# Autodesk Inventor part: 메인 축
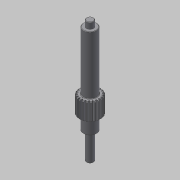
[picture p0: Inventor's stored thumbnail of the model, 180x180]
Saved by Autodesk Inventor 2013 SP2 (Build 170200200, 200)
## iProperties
Created: 2016-02
Part Number: 메인 축
Material: 일반
Document SubType Name: Modeling
Categories: <?xml version="1.0" encoding="UTF-16"?> <MemberInstance><Categories><FamilyTemplate><FamilyTemplateParameter ValueType="xs:double" Id="1" ObjectReferenceKey="da
Density: 1 g/cm^3
Mass: 187.503 g
Surface Area: 82.0529 cm^2
Volume: 23.8554 cm^3
Author: mdu
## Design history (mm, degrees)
sketch "Sketch1"
  geometry: C1 r 12 at (0, 0)
  constraints: 1 centre point
  dimensions: "d0" = 24 diameter of C1 (= da_da)
extrude "Extrusion1" new body sketch "Sketch1" distance "d1" = 20 (= da_b); taper "d2" = 0 deg
workplane "Work Plane2"
feature "피치 지름" dims "d4" = 10, "d5" = 0
workplane "Work Plane8"
workplane "Work Plane9"
chamfer "모따기1" distance "d49" = 1; stored, may be unused: second distance "d50" = 2, angle "d51" = 45 deg
sketch "스케치3"
  geometry: C1 r 7.5 at (0, 0); 1 further point
  constraints: 1 centre point, 1 coincident
  dimensions: "d52" = 15 diameter of C1
extrude "돌출2" join sketch "스케치3" distance "d53" = 66; taper "d54" = 0 deg
sketch "스케치4"
  geometry: C1 r 4 at (0, 0); 1 further point
  constraints: 1 centre point, 1 coincident
  dimensions: "d55" = 8 diameter of C1
extrude "돌출3" join sketch "스케치4" distance "d56" = 7; taper "d57" = 0 deg
sketch "스케치5"
  geometry: C1 r 7.5 at (0, 0) reference; C2 r 7.5 at (0, 0) reference; 1 further point
extrude "돌출4" join sketch "스케치5" distance "d62" = 16; taper "d63" = 0 deg
sketch "스케치6"
  geometry: C1 r 4 at (0, 0); 1 further point
  constraints: 1 centre point, 1 coincident
  dimensions: "d64" = 8 diameter of C1
extrude "돌출5" join sketch "스케치6" distance "d65" = 30; taper "d66" = 0 deg
chamfer "모따기2" distance "d58" = 0.5; stored, may be unused: second distance "d59" = 2, angle "d60" = 45 deg
fillet "모깎기1" dims "d61" = 0.5
feature "스퍼 기어" dims "da_b" = 20, "da_d" = 22, "da_aw" = 31, "da_da" = 24, "da_df" = 19.5, "da_dw" = 22, angle "da_beta" = 0 deg, "da_lefttooth" = 0, "da_righttooth" = 0
sketch "스케치7" dims "d68" = 18
  geometry: C1 r 0.25 at (0, -9); 2 further points
  constraints: 2 vertical alignment, 1 centre point, 1 coincident, 2 other
  dimensions: "d67" = 0.5 diameter of C1
extrude "돌출6" join sketch "스케치7" distance "d69" = 0.3; taper "d70" = 0 deg
body "Solid1"
sketch "Sketch2"
  geometry: C1 r 12 at (0, 0) reference; C2 r 11 at (0, 0)
  constraints: 1 centre point, 1 coincident
  dimensions: "d3" = 22 diameter of C2 (= da_dw)
body "Srf1"
node "투영된 루프1"
other parameters: "d16" = 31 (= da_aw), "d17" = 0, "d34" = 1.428 (computed from da_z), "d39" = 0, "d41" = 0, "d43" = 31 (= da_aw), "d46" = 31 (= da_aw), "d47" = 0, "d48" = 0
